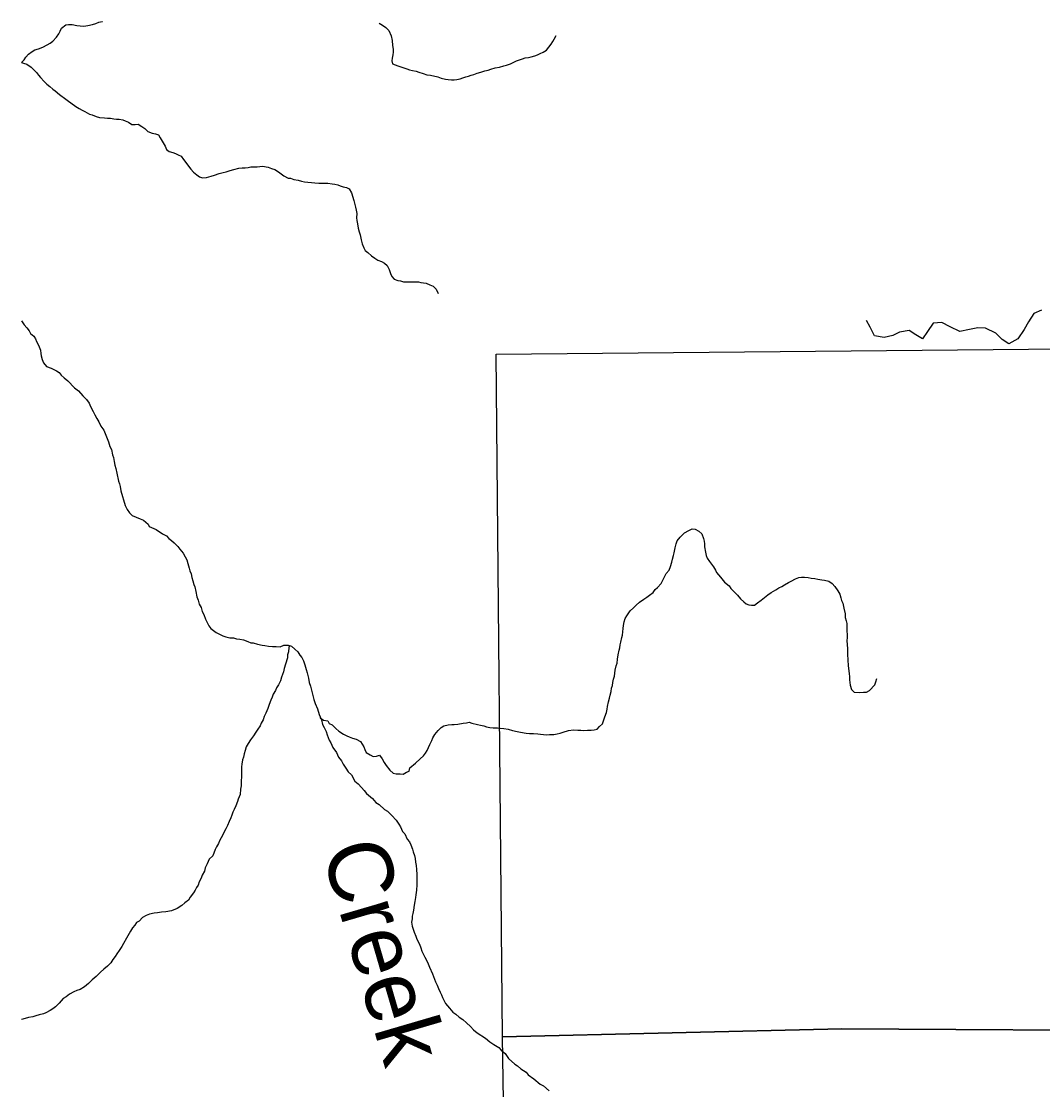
# Model space of a CAD drawing. Extents: x -21.1 to 50.3, y 0 to 22.1.
# Drawn here: x -21.052 to -19.541, y 20.525 to 22.105 of the extents above; entities that cross this region are included whole.
import ezdxf

# ---------------------------------------------------------------- set-up
doc = ezdxf.new("R2010")
doc.units = 0
for name, color, linetype in [('GM_X_Minor_River', 7, 'Continuous'), ('GM_X_Minor_River_Text', 7, 'Continuous'), ('GM_X_Section', 7, 'Continuous')]:
    doc.layers.add(name, color=color, linetype=linetype)

msp = doc.modelspace()

# ---------------------------------------------------------------- linework, layer by layer
at = {"layer": 'GM_X_Minor_River'}
for points in [[(-21.0521, 22.0443), (-21.0478, 22.0483), (-21.0455, 22.0525), (-21.0414, 22.0567), (-21.0361, 22.0609), (-21.0323, 22.0632), (-21.0267, 22.0647), (-21.0203, 22.067), (-21.0139, 22.0705), (-21.0093, 22.0728), (-21.0056, 22.0762), (-21.0003, 22.082), (-20.9969, 22.0869), (-20.9947, 22.0907), (-20.9925, 22.0953), (-20.9864, 22.1003), (-20.9823, 22.1007), (-20.977, 22.1007), (-20.9702, 22.0992), (-20.9649, 22.0985), (-20.9596, 22.0982), (-20.9539, 22.0993), (-20.9471, 22.1005), (-20.9418, 22.1021), (-20.9377, 22.104), (-20.9327, 22.1051), (-20.9321, 22.1053)], [(-20.5225, 22.1028), (-20.518, 22.0998), (-20.5127, 22.0964), (-20.5085, 22.0918), (-20.505, 22.0839), (-20.5034, 22.077), (-20.503, 22.0698), (-20.5022, 22.0641), (-20.5022, 22.0599), (-20.5025, 22.0557), (-20.5033, 22.0508), (-20.504, 22.047), (-20.5032, 22.0424), (-20.4952, 22.0394), (-20.4861, 22.0364), (-20.4816, 22.0353), (-20.4778, 22.0338), (-20.4732, 22.0327), (-20.4679, 22.0316), (-20.4638, 22.0301), (-20.4577, 22.0282), (-20.452, 22.0264), (-20.4467, 22.0256), (-20.4361, 22.023), (-20.4308, 22.0215), (-20.4243, 22.0197), (-20.4205, 22.0193), (-20.4156, 22.0189), (-20.4115, 22.0186), (-20.4077, 22.0194), (-20.4028, 22.0205), (-20.399, 22.0217), (-20.3945, 22.0232), (-20.3903, 22.0244), (-20.3865, 22.0256), (-20.3824, 22.0267), (-20.3775, 22.0287), (-20.3722, 22.0302), (-20.3665, 22.0321), (-20.3616, 22.0329), (-20.3575, 22.0345), (-20.351, 22.0364), (-20.3446, 22.0376), (-20.3382, 22.0395), (-20.3344, 22.0403), (-20.3284, 22.0426), (-20.3235, 22.0449), (-20.3193, 22.0468), (-20.3148, 22.0484), (-20.3106, 22.0499), (-20.3065, 22.0511), (-20.3016, 22.0519), (-20.2978, 22.053), (-20.2921, 22.0542), (-20.2884, 22.0557), (-20.2846, 22.0577), (-20.2801, 22.0596), (-20.2752, 22.0627), (-20.2714, 22.0672), (-20.2684, 22.0714), (-20.2658, 22.0753), (-20.2636, 22.0791), (-20.2609, 22.0844)], [(-21.0521, 22.0443), (-21.0492, 22.0433), (-21.0439, 22.0418), (-21.0378, 22.0377), (-21.0336, 22.0335), (-21.0295, 22.0297), (-21.0268, 22.0259), (-21.0237, 22.0222), (-21.0184, 22.0161), (-21.0142, 22.0123), (-21.01, 22.0089), (-21.0058, 22.0052), (-21.002, 22.0025), (-20.9955, 21.9972), (-20.9864, 21.9904), (-20.9826, 21.9874), (-20.9788, 21.9848), (-20.9716, 21.9795), (-20.9666, 21.9765), (-20.9621, 21.9738), (-20.9583, 21.972), (-20.9511, 21.9682), (-20.9473, 21.9671), (-20.9416, 21.9648), (-20.9363, 21.9629), (-20.9291, 21.9626), (-20.9245, 21.9623), (-20.9204, 21.9619), (-20.9154, 21.9612), (-20.9113, 21.9608), (-20.9075, 21.9604), (-20.9022, 21.9597), (-20.8984, 21.9582), (-20.8938, 21.956), (-20.8889, 21.9529), (-20.8836, 21.9526), (-20.8791, 21.9534), (-20.8737, 21.95), (-20.8696, 21.9466), (-20.865, 21.9424), (-20.8585, 21.9398), (-20.8536, 21.9391), (-20.8494, 21.9376), (-20.8468, 21.933), (-20.8422, 21.9254), (-20.8395, 21.9205), (-20.8372, 21.9156), (-20.8334, 21.9126), (-20.8281, 21.9111), (-20.8239, 21.9096), (-20.8201, 21.9081), (-20.8155, 21.9058), (-20.8121, 21.9009), (-20.8075, 21.8948), (-20.8048, 21.891), (-20.8014, 21.8865), (-20.7976, 21.8823), (-20.7926, 21.8782), (-20.7884, 21.8752), (-20.7839, 21.8737), (-20.7782, 21.8745), (-20.7714, 21.8764), (-20.7661, 21.8779), (-20.7593, 21.8803), (-20.7533, 21.8818), (-20.7491, 21.8826), (-20.7431, 21.8845), (-20.7378, 21.8861), (-20.7303, 21.888), (-20.7254, 21.8888), (-20.7212, 21.8888), (-20.7167, 21.8892), (-20.7125, 21.89), (-20.7034, 21.8901), (-20.6951, 21.8909), (-20.6868, 21.8894), (-20.6818, 21.8879)], [(-20.6818, 21.8879), (-20.6773, 21.886), (-20.6716, 21.8826), (-20.6636, 21.877), (-20.6575, 21.8736), (-20.6537, 21.8732), (-20.6492, 21.8713), (-20.6424, 21.8702), (-20.6374, 21.8691), (-20.6333, 21.868), (-20.6181, 21.8666), (-20.612, 21.8658), (-20.6071, 21.8659), (-20.6022, 21.8659), (-20.5984, 21.8659), (-20.592, 21.8652), (-20.5882, 21.8645), (-20.584, 21.8633), (-20.5802, 21.8622), (-20.5761, 21.8607), (-20.5711, 21.8596), (-20.567, 21.8577), (-20.5635, 21.8517), (-20.56, 21.8403), (-20.5589, 21.8346), (-20.5577, 21.8304), (-20.5569, 21.8258), (-20.5557, 21.8209), (-20.5561, 21.8148), (-20.5557, 21.811), (-20.5549, 21.8057), (-20.5537, 21.7993), (-20.5521, 21.7939), (-20.551, 21.7898), (-20.5494, 21.7822), (-20.5478, 21.7761), (-20.5455, 21.7704), (-20.5432, 21.7666), (-20.5394, 21.7632), (-20.5341, 21.7583), (-20.5291, 21.7549), (-20.5246, 21.7523), (-20.5193, 21.75), (-20.5147, 21.7478), (-20.5109, 21.744), (-20.5078, 21.7383), (-20.5059, 21.7326), (-20.504, 21.728), (-20.5005, 21.7239), (-20.4952, 21.722), (-20.4911, 21.7213), (-20.4865, 21.7202), (-20.4684, 21.7203), (-20.4646, 21.7199), (-20.4608, 21.7192), (-20.4532, 21.7181), (-20.4475, 21.7154), (-20.4426, 21.7136), (-20.4384, 21.709), (-20.4353, 21.7029)], [(-19.5425, 21.6783), (-19.5542, 21.6733), (-19.5617, 21.6611), (-19.5684, 21.6496), (-19.5778, 21.6359), (-19.591, 21.6282), (-19.6009, 21.635), (-19.6104, 21.644), (-19.6256, 21.6515), (-19.6369, 21.6518), (-19.649, 21.6494), (-19.6634, 21.6467), (-19.6778, 21.6534), (-19.69, 21.6601), (-19.7028, 21.6589), (-19.7114, 21.6467), (-19.7189, 21.6356), (-19.7284, 21.6416), (-19.7383, 21.648), (-19.7527, 21.6456), (-19.7625, 21.6406), (-19.7753, 21.6375), (-19.7897, 21.6401), (-19.7962, 21.6529), (-19.8016, 21.6631)], [(-21.0521, 21.6625), (-21.051, 21.6609), (-21.048, 21.6567), (-21.0442, 21.6522), (-21.0407, 21.6476), (-21.0384, 21.6438), (-21.0339, 21.6397), (-21.0312, 21.6359), (-21.0296, 21.6317), (-21.027, 21.6264), (-21.0239, 21.6192)], [(-21.0239, 21.6192), (-21.0231, 21.6143), (-21.0227, 21.6105), (-21.0215, 21.6052), (-21.0196, 21.6002), (-21.015, 21.5949), (-21.0078, 21.5923), (-21.0002, 21.5885), (-20.996, 21.5859), (-20.993, 21.5821), (-20.9888, 21.578), (-20.9834, 21.5738), (-20.9735, 21.5632), (-20.9678, 21.5591), (-20.961, 21.5515), (-20.9556, 21.5458), (-20.9518, 21.5405), (-20.9499, 21.5356), (-20.946, 21.5284), (-20.9433, 21.5235), (-20.9403, 21.5178), (-20.9376, 21.5132), (-20.9345, 21.5068), (-20.9303, 21.5007), (-20.9269, 21.4931), (-20.923, 21.4833), (-20.9211, 21.4764), (-20.9188, 21.4723), (-20.9172, 21.4643), (-20.916, 21.4605), (-20.9149, 21.4544), (-20.9137, 21.4487), (-20.9125, 21.4442), (-20.9109, 21.437), (-20.9082, 21.4252), (-20.9067, 21.4214), (-20.9059, 21.4176), (-20.9047, 21.4108), (-20.9024, 21.4024), (-20.9008, 21.3975), (-20.8985, 21.3891), (-20.8954, 21.3835), (-20.892, 21.3785), (-20.8882, 21.3747), (-20.8764, 21.3695), (-20.8715, 21.3676), (-20.8646, 21.3619), (-20.8631, 21.3582), (-20.8528, 21.3537), (-20.8433, 21.3476), (-20.8376, 21.3446), (-20.8338, 21.3404), (-20.83, 21.3374), (-20.8258, 21.334), (-20.8205, 21.3287), (-20.8178, 21.3249), (-20.8129, 21.3189), (-20.8098, 21.3136), (-20.8075, 21.3087), (-20.8059, 21.3037), (-20.8036, 21.2965), (-20.8028, 21.2927), (-20.8009, 21.2882), (-20.7997, 21.2828), (-20.7982, 21.2779), (-20.797, 21.2726), (-20.7955, 21.2688), (-20.7939, 21.2623), (-20.7923, 21.2544), (-20.7904, 21.2494), (-20.7889, 21.2434), (-20.7862, 21.2384), (-20.7846, 21.2327), (-20.7823, 21.2282), (-20.7796, 21.2214), (-20.7765, 21.2153), (-20.7746, 21.2111), (-20.7719, 21.2073), (-20.764, 21.2013), (-20.7598, 21.1994), (-20.7541, 21.1964), (-20.7495, 21.1949), (-20.7439, 21.1938), (-20.7382, 21.1935), (-20.7336, 21.1923), (-20.7291, 21.1916), (-20.7234, 21.1905), (-20.7169, 21.1883), (-20.7128, 21.1864), (-20.709, 21.186), (-20.7029, 21.1841), (-20.6957, 21.1827), (-20.6919, 21.1823), (-20.6862, 21.1812), (-20.6806, 21.1808), (-20.6749, 21.1809), (-20.6692, 21.1805), (-20.6636, 21.1828), (-20.6575, 21.1829), (-20.6526, 21.1814), (-20.6476, 21.1768)], [(-20.1758, 21.1326), (-20.1747, 21.1368), (-20.174, 21.1414), (-20.1733, 21.1459), (-20.1718, 21.152), (-20.1707, 21.1562), (-20.17, 21.1619), (-20.1689, 21.1684), (-20.1678, 21.1752), (-20.1667, 21.179), (-20.166, 21.1832), (-20.1652, 21.187), (-20.1638, 21.1939), (-20.1627, 21.1977), (-20.1619, 21.2022), (-20.1616, 21.2072), (-20.1609, 21.2118), (-20.1602, 21.2171), (-20.1587, 21.222), (-20.1561, 21.2262), (-20.1512, 21.2335), (-20.1463, 21.2377), (-20.1422, 21.2419), (-20.1373, 21.2465), (-20.1309, 21.2507), (-20.1264, 21.2538), (-20.1226, 21.2568), (-20.1173, 21.2606), (-20.1143, 21.2652), (-20.1106, 21.2679), (-20.1053, 21.274), (-20.1031, 21.279), (-20.0982, 21.2885), (-20.0937, 21.2938), (-20.0915, 21.2992), (-20.0896, 21.3053), (-20.0885, 21.3098), (-20.0874, 21.3152), (-20.0863, 21.3194), (-20.0849, 21.3266), (-20.083, 21.3327), (-20.0815, 21.3369), (-20.0774, 21.3426), (-20.0707, 21.3487), (-20.0646, 21.3525), (-20.0597, 21.3548), (-20.0552, 21.3541), (-20.0495, 21.3511), (-20.0453, 21.3473), (-20.043, 21.3405), (-20.0418, 21.3363), (-20.0414, 21.3325), (-20.0414, 21.3283), (-20.0398, 21.3204), (-20.039, 21.3154), (-20.0375, 21.3116), (-20.034, 21.3067), (-20.0279, 21.2988), (-20.0252, 21.2938), (-20.0233, 21.29), (-20.0176, 21.2832), (-20.0119, 21.2757), (-20.005, 21.2707), (-20.0023, 21.2666), (-19.9966, 21.2605), (-19.9924, 21.2567), (-19.9882, 21.2514), (-19.9833, 21.2469), (-19.9795, 21.2439), (-19.9757, 21.2424), (-19.9719, 21.2417), (-19.9674, 21.2421), (-19.9628, 21.2451), (-19.9576, 21.2493), (-19.9478, 21.257), (-19.9425, 21.2604), (-19.9357, 21.2647), (-19.9312, 21.2673), (-19.9267, 21.2693), (-19.9229, 21.2719), (-19.9169, 21.2754), (-19.9131, 21.2773), (-19.9067, 21.2808), (-19.9018, 21.2827), (-19.898, 21.2831), (-19.8935, 21.2835), (-19.8878, 21.2828), (-19.8833, 21.282), (-19.878, 21.2813), (-19.8738, 21.2802), (-19.8677, 21.2795), (-19.8636, 21.2787), (-19.8575, 21.2772), (-19.8522, 21.2738), (-19.8484, 21.2697), (-19.8438, 21.2629), (-19.8411, 21.2583), (-19.8395, 21.2526), (-19.8384, 21.2488), (-19.8368, 21.2447), (-19.8349, 21.2374)], [(-19.8349, 21.2374), (-19.8333, 21.2291), (-19.8329, 21.2238), (-19.8317, 21.2185), (-19.8309, 21.2147), (-19.8305, 21.2097), (-19.8309, 21.2036), (-19.8304, 21.1987), (-19.8304, 21.1941), (-19.8308, 21.1892), (-19.8303, 21.1835), (-19.8299, 21.1774), (-19.8299, 21.1687), (-19.8294, 21.1611), (-19.8286, 21.1523), (-19.8274, 21.1409), (-19.8266, 21.136), (-19.8266, 21.1314), (-19.8262, 21.1276), (-19.8257, 21.1234), (-19.8238, 21.117), (-19.8196, 21.1132), (-19.8113, 21.1125), (-19.806, 21.1133), (-19.8015, 21.1133), (-19.7969, 21.1156), (-19.7894, 21.124), (-19.7876, 21.1286), (-19.7865, 21.1332)], [(-20.6556, 21.1823), (-20.6563, 21.1795), (-20.6567, 21.173), (-20.6582, 21.1684), (-20.6585, 21.1639), (-20.6611, 21.1547), (-20.6633, 21.1482), (-20.664, 21.1433), (-20.6655, 21.1391), (-20.667, 21.1353), (-20.6689, 21.13), (-20.6715, 21.1239), (-20.6748, 21.1197), (-20.6763, 21.1155), (-20.6797, 21.1101), (-20.6808, 21.106), (-20.683, 21.1014), (-20.6853, 21.0949), (-20.6875, 21.0892), (-20.6905, 21.082), (-20.6927, 21.077), (-20.6945, 21.0721), (-20.6972, 21.0675), (-20.699, 21.0633), (-20.7024, 21.0583), (-20.705, 21.0541), (-20.7084, 21.0488), (-20.7129, 21.0427), (-20.7166, 21.0373), (-20.7196, 21.0324), (-20.7211, 21.0271), (-20.7226, 21.0221), (-20.7233, 21.0172), (-20.7248, 21.0133), (-20.7259, 21.0069), (-20.7262, 21.0027), (-20.7262, 20.9981), (-20.7265, 20.9924), (-20.7265, 20.9871), (-20.7268, 20.9829), (-20.7268, 20.9791), (-20.7271, 20.9746), (-20.7279, 20.9696), (-20.7286, 20.962), (-20.7312, 20.9552), (-20.7323, 20.9513), (-20.7349, 20.9453), (-20.7371, 20.9399), (-20.739, 20.9357), (-20.7405, 20.9315), (-20.7423, 20.9273), (-20.7446, 20.922), (-20.7472, 20.9159), (-20.7498, 20.911), (-20.7524, 20.9056), (-20.7546, 20.9014), (-20.7565, 20.8976), (-20.7587, 20.8934), (-20.7606, 20.8892), (-20.7632, 20.8843), (-20.7655, 20.8805), (-20.7688, 20.8713), (-20.7741, 20.866), (-20.777, 20.8591), (-20.78, 20.8534), (-20.7811, 20.8484), (-20.7845, 20.8427), (-20.786, 20.8382), (-20.789, 20.8328), (-20.7904, 20.8279), (-20.7931, 20.8241), (-20.7949, 20.8202), (-20.7972, 20.8164), (-20.8024, 20.8099), (-20.805, 20.8054), (-20.8103, 20.8015), (-20.8148, 20.7977), (-20.8216, 20.7931), (-20.8299, 20.79), (-20.8382, 20.7885), (-20.845, 20.7877), (-20.8507, 20.7869), (-20.8556, 20.7865), (-20.8624, 20.7849), (-20.8677, 20.783), (-20.873, 20.7799), (-20.8778, 20.7746), (-20.8816, 20.7726), (-20.8842, 20.7688), (-20.8876, 20.7646), (-20.8906, 20.76), (-20.8928, 20.7562), (-20.8966, 20.7494), (-20.9011, 20.7417), (-20.9037, 20.7372), (-20.9074, 20.7314), (-20.9108, 20.7261), (-20.9134, 20.7223), (-20.9168, 20.7177), (-20.9198, 20.7128), (-20.9247, 20.7082)], [(-20.6476, 21.1768), (-20.643, 21.1727), (-20.64, 21.1681), (-20.6369, 21.1644), (-20.6346, 21.1598), (-20.6327, 21.1534), (-20.6308, 21.1465), (-20.6292, 21.142), (-20.6273, 21.134), (-20.6261, 21.1275), (-20.6245, 21.1222), (-20.6226, 21.1162), (-20.6214, 21.1105), (-20.6195, 21.1025), (-20.6175, 21.0964), (-20.6141, 21.0888), (-20.6114, 21.0801), (-20.6079, 21.0721), (-20.6067, 21.0653), (-20.604, 21.0611), (-20.6013, 21.0551), (-20.5998, 21.0501), (-20.5967, 21.0422), (-20.594, 21.0384), (-20.591, 21.0312), (-20.586, 21.024), (-20.5829, 21.0171), (-20.5783, 21.0115), (-20.576, 21.0069), (-20.5718, 21.0009), (-20.5684, 20.9956), (-20.5638, 20.991), (-20.5588, 20.9815), (-20.5539, 20.9778), (-20.5489, 20.9721), (-20.5447, 20.9676), (-20.5413, 20.9634), (-20.5325, 20.9562), (-20.5276, 20.9498), (-20.5226, 20.9471), (-20.515, 20.9396), (-20.5104, 20.9373), (-20.504, 20.9309), (-20.4975, 20.9237), (-20.4937, 20.918), (-20.491, 20.9142), (-20.4883, 20.907), (-20.4845, 20.9036), (-20.4814, 20.896), (-20.478, 20.8919), (-20.4757, 20.8873), (-20.4733, 20.8809), (-20.4722, 20.8771), (-20.4706, 20.8718), (-20.4695, 20.8672), (-20.4687, 20.8619), (-20.4679, 20.857), (-20.4674, 20.8509), (-20.467, 20.8437), (-20.4669, 20.8281), (-20.4676, 20.8205), (-20.4683, 20.8136), (-20.469, 20.8094), (-20.4698, 20.8037), (-20.4709, 20.798), (-20.4719, 20.7908), (-20.4727, 20.7859), (-20.4738, 20.782), (-20.4741, 20.7782), (-20.4748, 20.7729), (-20.474, 20.7672), (-20.4709, 20.7581), (-20.4686, 20.7524), (-20.4671, 20.7479), (-20.4629, 20.7403), (-20.4609, 20.735), (-20.4594, 20.7304), (-20.4575, 20.7263), (-20.4552, 20.7213), (-20.451, 20.7141), (-20.4483, 20.7065), (-20.444, 20.6967), (-20.4394, 20.6849), (-20.4367, 20.68), (-20.4348, 20.6751), (-20.4325, 20.6697), (-20.4306, 20.6656), (-20.429, 20.6618), (-20.4244, 20.6527), (-20.4187, 20.6459), (-20.4137, 20.6398), (-20.4092, 20.6372), (-20.4042, 20.6326), (-20.3989, 20.6292), (-20.3936, 20.624), (-20.3875, 20.619), (-20.3829, 20.6137), (-20.3776, 20.6092), (-20.3654, 20.6013), (-20.3589, 20.596), (-20.3532, 20.5922)], [(-20.6101, 21.0772), (-20.6102, 21.0755), (-20.6049, 21.0718), (-20.5984, 21.0707), (-20.5965, 21.0669), (-20.592, 21.065), (-20.587, 21.0597), (-20.5824, 21.0555), (-20.5756, 21.051), (-20.5706, 21.0488), (-20.5669, 21.0473), (-20.5623, 21.0454), (-20.5566, 21.0435), (-20.5501, 21.0401), (-20.5479, 21.0363), (-20.5452, 21.0326), (-20.544, 21.0284), (-20.5417, 21.0242), (-20.536, 21.0204), (-20.5315, 21.0182), (-20.5265, 21.0186), (-20.522, 21.0198), (-20.5182, 21.0148), (-20.5151, 21.0091), (-20.5124, 21.0046), (-20.5071, 20.9978), (-20.5018, 20.9936), (-20.4976, 20.9925), (-20.4915, 20.9922), (-20.4874, 20.9918), (-20.4821, 20.9949), (-20.4783, 20.9964), (-20.4772, 21.0014), (-20.4689, 21.0083), (-20.4622, 21.0148), (-20.4569, 21.0193), (-20.4539, 21.0232), (-20.4517, 21.027), (-20.4498, 21.0312), (-20.4476, 21.0357), (-20.445, 21.0418), (-20.4435, 21.0456), (-20.4401, 21.0506), (-20.4352, 21.0563), (-20.4311, 21.0609), (-20.427, 21.0636), (-20.4205, 21.0648), (-20.4152, 21.0652), (-20.4115, 21.0656), (-20.4062, 21.066), (-20.3982, 21.0672), (-20.3937, 21.068), (-20.3895, 21.0687), (-20.3857, 21.0676), (-20.377, 21.0654), (-20.3729, 21.0643), (-20.3679, 21.0632), (-20.3641, 21.062), (-20.3588, 21.0609), (-20.3539, 21.0606), (-20.3475, 21.0606), (-20.3437, 21.0602), (-20.338, 21.0595), (-20.3319, 21.0584), (-20.3255, 21.0565), (-20.3183, 21.0551), (-20.3138, 21.0539), (-20.3054, 21.0528), (-20.3001, 21.0521), (-20.2941, 21.0521), (-20.288, 21.0518), (-20.2842, 21.0511), (-20.2751, 21.0503), (-20.2706, 21.0504), (-20.2642, 21.0508), (-20.2592, 21.0516), (-20.2551, 21.0527), (-20.2502, 21.0543), (-20.2426, 21.0566), (-20.2351, 21.0574), (-20.2286, 21.0571), (-20.2241, 21.0571), (-20.2199, 21.0567), (-20.2143, 21.0568), (-20.209, 21.0572), (-20.2044, 21.0576), (-20.1999, 21.0587), (-20.1969, 21.0625), (-20.192, 21.0664), (-20.1887, 21.0767), (-20.1864, 21.0831), (-20.1853, 21.0881), (-20.1846, 21.0919), (-20.1831, 21.0987), (-20.1821, 21.1044), (-20.1809, 21.1086), (-20.1795, 21.114), (-20.1788, 21.1189), (-20.1776, 21.1231), (-20.1769, 21.1277), (-20.1758, 21.1326)], [(-20.9247, 20.7082), (-20.9299, 20.7036), (-20.9348, 20.699), (-20.9412, 20.6929), (-20.9472, 20.6879), (-20.9529, 20.6825), (-20.9589, 20.6772), (-20.9649, 20.6737), (-20.9702, 20.6718), (-20.9743, 20.6699), (-20.9811, 20.6668), (-20.9856, 20.6626), (-20.9902, 20.6603), (-20.9962, 20.6534), (-21.0018, 20.6477), (-21.0056, 20.645), (-21.0097, 20.6423), (-21.0157, 20.6389), (-21.0195, 20.6373), (-21.0256, 20.6358), (-21.0305, 20.6346), (-21.0354, 20.6331), (-21.0418, 20.6319), (-21.0501, 20.6296), (-21.0521, 20.6292)], [(-20.3532, 20.5922), (-20.3456, 20.5877), (-20.3422, 20.5839), (-20.3361, 20.579), (-20.3311, 20.5714), (-20.322, 20.5631), (-20.3178, 20.5605), (-20.3132, 20.556), (-20.3053, 20.5514), (-20.3022, 20.5473), (-20.2938, 20.5416), (-20.2847, 20.5333), (-20.2794, 20.531), (-20.271, 20.5235)]]:
    msp.add_lwpolyline(points, dxfattribs=at)
at = {"layer": 'GM_X_Section'}
for points in [[(-19.3519, 21.6226), (-19.3314, 20.6124), (-19.8379, 20.6155), (-20.3404, 20.6033), (-20.3496, 21.6129)], [(-19.3314, 20.6124), (-19.3154, 19.6017), (-20.3244, 19.59), (-20.3404, 20.6033), (-19.8379, 20.6155)]]:
    msp.add_lwpolyline(points, close=True, dxfattribs=at)

# ---------------------------------------------------------------- texts
at = {"layer": 'GM_X_Minor_River_Text'}
msp.add_text('Creek', height=0.09472, rotation=286.3039, dxfattribs=at).set_placement((-20.6084, 20.88))

doc.saveas('drawing.dxf')
